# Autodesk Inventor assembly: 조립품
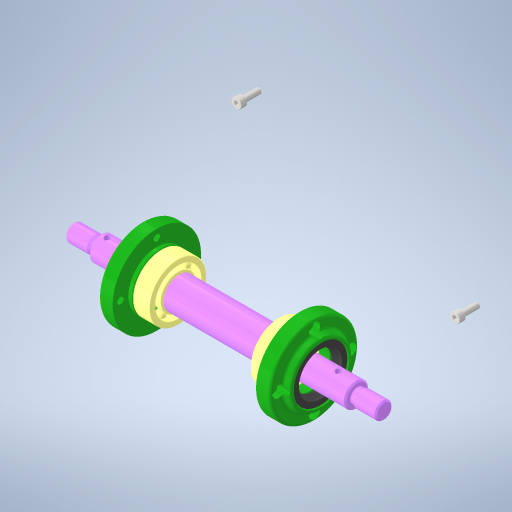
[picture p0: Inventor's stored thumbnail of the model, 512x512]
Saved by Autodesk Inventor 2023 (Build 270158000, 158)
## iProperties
Created: 2025-04
Part Number: 조립품
Document SubType Name: Assembly
Designer: ADMIN_PC
Author: ADMIN_PC
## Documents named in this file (7)
- C:\Users\ADMIN_PC\Downloads\750406V1006\조립품.iam
- C:\Users\ADMIN_PC\Downloads\750406V1006\본체.ipt
- C:\Users\ADMIN_PC\Downloads\750406V1006\깊은 홈 볼 베어링 6203.ipt
- C:\Users\ADMIN_PC\Downloads\750406V1006\축.ipt
- C:\Users\ADMIN_PC\Downloads\750406V1006\커버.ipt
- C:\Users\ADMIN_PC\Downloads\750406V1006\오일 실 26 38 8.ipt
- C:\Users\ADMIN_PC\Downloads\750406V1006\6각 구멍붙이 볼트 M4x12.ipt
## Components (2 placed, 1 different names)
1. 6각 구멍붙이 볼트 M4x12:1
2. 6각 구멍붙이 볼트 M4x12:2
